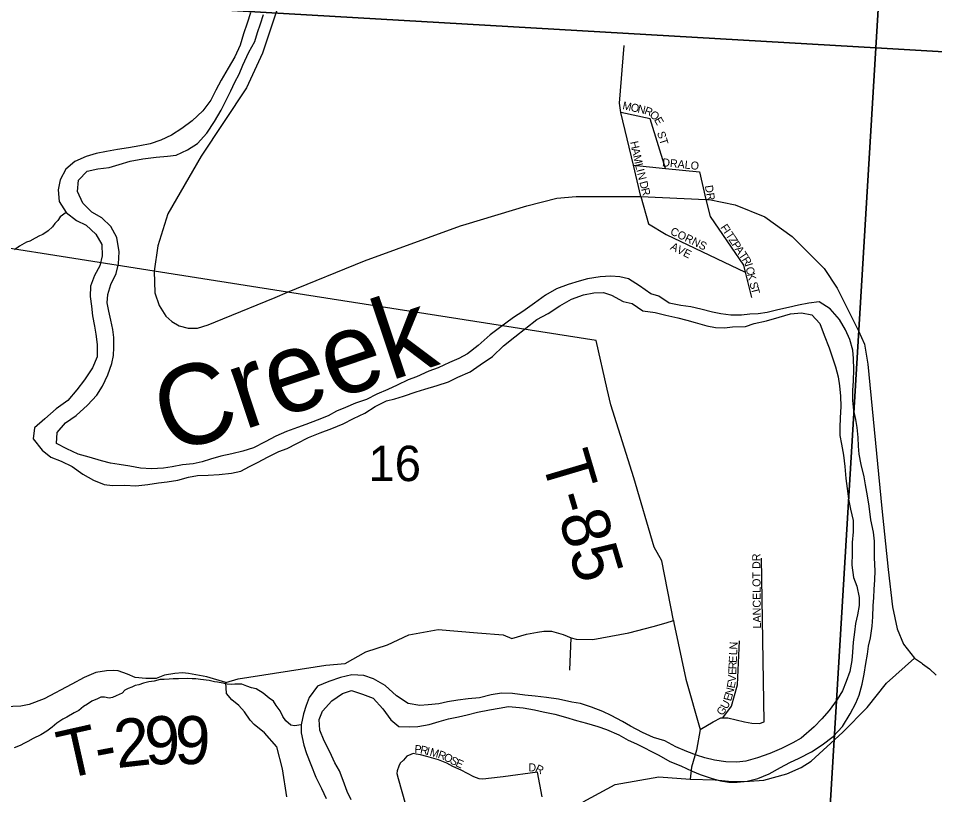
# Model space of a CAD drawing. Extents: x 0 to 34, y 0 to 22.
# Drawn here: x 4.831 to 5.915, y 18.127 to 19.045 of the extents above; entities that cross this region are included whole.
import ezdxf

# ---------------------------------------------------------------- set-up
doc = ezdxf.new("R2010")
doc.units = 0
for name, color, linetype in [('GM_X_County_Road', 7, 'Continuous'), ('GM_X_Major_River', 7, 'Continuous'), ('GM_X_Major_River_Text', 7, 'Continuous'), ('GM_X_Minor_River', 7, 'Continuous'), ('GM_X_Section', 7, 'Continuous'), ('GM_X_Section_Text', 7, 'Continuous'), ('GM_X_State_Route', 7, 'Continuous'), ('GM_X_Township_Road', 7, 'Continuous'), ('GM_X_Township_Road_Text', 7, 'Continuous'), ('GM_X_Township_ROW', 7, 'Continuous'), ('GM_X_Township_Subdivision', 7, 'Continuous'), ('GM_X_Township_Subdivision_Text', 7, 'Continuous')]:
    doc.layers.add(name, color=color, linetype=linetype)

msp = doc.modelspace()

# ---------------------------------------------------------------- linework, layer by layer
at = {"layer": 'GM_X_County_Road'}
for points in [[(5.1491, 18.1244), (5.1438, 18.1574), (5.137, 18.1832), (5.1226, 18.1999), (5.1104, 18.2098), (5.1055, 18.2151), (5.099, 18.2246), (5.0922, 18.2321), (5.0839, 18.239), (5.0774, 18.2466), (5.077, 18.2596), (5.0914, 18.2637), (5.1949, 18.28), (5.218, 18.2819), (5.2423, 18.2956), (5.2681, 18.304), (5.2931, 18.3158), (5.3279, 18.3222), (5.3746, 18.3181), (5.4049, 18.3158), (5.415, 18.3116), (5.4325, 18.3165), (5.4454, 18.3189), (5.4529, 18.3203), (5.4619, 18.3203), (5.476, 18.3163), (5.4852, 18.3125), (5.4911, 18.3107), (5.5109, 18.3104), (5.5535, 18.3184), (5.5824, 18.3259), (5.5975, 18.3302), (5.6064, 18.333), (5.6069, 18.3302)], [(5.6069, 18.3302), (5.6208, 18.2633), (5.6377, 18.2039), (5.6336, 18.1794), (5.6275, 18.1594), (5.6259, 18.145)], [(5.4994, 18.1185), (5.5373, 18.1387), (5.589, 18.1478), (5.6259, 18.145), (5.6557, 18.1442), (5.6713, 18.1427), (5.6906, 18.1423), (5.7133, 18.144), (5.7402, 18.1515), (5.7572, 18.1589), (5.769, 18.1664), (5.8067, 18.2007), (5.8355, 18.23), (5.8582, 18.2585), (5.8915, 18.2884)]]:
    msp.add_lwpolyline(points, dxfattribs=at)
at = {"layer": 'GM_X_Major_River'}
for points in [[(5.106, 19.0516), (5.1022, 19.0395), (5.0977, 19.0266), (5.0936, 19.0133), (5.0876, 18.9996), (5.0796, 18.986), (5.0714, 18.9719), (5.0649, 18.9602), (5.0589, 18.9484), (5.0495, 18.9358), (5.037, 18.9237), (5.0246, 18.9149), (5.0125, 18.9069), (5, 18.9008), (4.9875, 18.8966), (4.975, 18.8943), (4.9618, 18.892), (4.9485, 18.8901), (4.9357, 18.8877), (4.9236, 18.8851), (4.9115, 18.8816), (4.8982, 18.8759), (4.8877, 18.8668), (4.8809, 18.8542), (4.8783, 18.8421), (4.8798, 18.8284), (4.8878, 18.8156), (4.9003, 18.8061), (4.9117, 18.8005), (4.9231, 18.7899), (4.9303, 18.7774), (4.9307, 18.7641), (4.9277, 18.7524), (4.9213, 18.741), (4.9168, 18.7284), (4.9165, 18.7159), (4.918, 18.7046), (4.9192, 18.6932), (4.9215, 18.6811), (4.923, 18.6716), (4.9246, 18.6591), (4.9246, 18.6447), (4.919, 18.6318), (4.9095, 18.6173), (4.9005, 18.6055), (4.8899, 18.593), (4.8763, 18.5831), (4.8627, 18.5713), (4.8503, 18.5607), (4.8488, 18.5478), (4.8594, 18.5341), (4.87, 18.5262), (4.8822, 18.5213), (4.8951, 18.5149), (4.9076, 18.5058), (4.9201, 18.4987), (4.933, 18.4938), (4.9428, 18.4923), (4.9572, 18.4927)], [(4.9408, 18.799), (4.9302, 18.8092), (4.9185, 18.8157), (4.9078, 18.8266), (4.9014, 18.8403), (4.9025, 18.8535), (4.9127, 18.8642), (4.9255, 18.8672), (4.9388, 18.8688), (4.9505, 18.8722), (4.9637, 18.8761), (4.9785, 18.8788), (4.9944, 18.8807), (5.008, 18.8819), (5.0182, 18.8831), (5.0314, 18.8895), (5.0432, 18.8971), (5.0545, 18.9093), (5.0635, 18.923), (5.0714, 18.9363), (5.0771, 18.9484), (5.0827, 18.9594), (5.0873, 18.9697), (5.0925, 18.9792), (5.097, 18.9898), (5.1042, 19.005), (5.111, 19.0175), (5.1144, 19.0285), (5.1177, 19.0384), (5.1215, 19.0498)], [(5.8149, 18.6651), (5.8099, 18.6768), (5.8027, 18.689), (5.7917, 18.7014), (5.7788, 18.7097), (5.7663, 18.7082), (5.7542, 18.7059), (5.7425, 18.7032), (5.7296, 18.7001), (5.7171, 18.697), (5.7065, 18.6955), (5.6967, 18.6951), (5.6869, 18.6939), (5.674, 18.6939), (5.6623, 18.6954), (5.6524, 18.6976), (5.6388, 18.701), (5.627, 18.704), (5.6149, 18.7055), (5.6013, 18.7081), (5.5891, 18.7164), (5.5797, 18.7194), (5.566, 18.7288), (5.5531, 18.7371), (5.5429, 18.7394), (5.5323, 18.7401), (5.5194, 18.7393), (5.5047, 18.737), (5.4948, 18.7343), (5.4816, 18.7301), (5.468, 18.7251), (5.4551, 18.7175), (5.4419, 18.7083), (5.4283, 18.6984), (5.417, 18.6912), (5.4007, 18.679), (5.3894, 18.6707), (5.3754, 18.6581), (5.3626, 18.6482), (5.3524, 18.6429), (5.3414, 18.6379), (5.3278, 18.6318), (5.3168, 18.6276), (5.3025, 18.6211), (5.2926, 18.6173), (5.2794, 18.6112), (5.2684, 18.6062), (5.2556, 18.6005), (5.2431, 18.5944), (5.2302, 18.5898), (5.2185, 18.5848), (5.2076, 18.5803), (5.1977, 18.5749), (5.1849, 18.5696), (5.1713, 18.5646), (5.1614, 18.5612), (5.1486, 18.5562), (5.1361, 18.5509), (5.1232, 18.544), (5.1096, 18.5371), (5.0968, 18.5333), (5.0839, 18.5298), (5.071, 18.5272), (5.0586, 18.5237), (5.0487, 18.5206), (5.0381, 18.518), (5.0256, 18.5168), (5.0135, 18.5145), (5.0029, 18.5129), (4.9889, 18.5121), (4.9757, 18.5129), (4.9632, 18.5155), (4.9507, 18.5173), (4.9405, 18.5188), (4.9299, 18.5215), (4.9151, 18.526), (4.9022, 18.5297), (4.8889, 18.5357), (4.8764, 18.5422), (4.8775, 18.5551), (4.887, 18.5665), (4.8998, 18.5752), (4.913, 18.5874), (4.9243, 18.5995), (4.9308, 18.6098), (4.9372, 18.6235), (4.942, 18.6368), (4.9439, 18.6462), (4.9443, 18.6557), (4.9442, 18.6675), (4.9431, 18.677), (4.9408, 18.6879), (4.9385, 18.6986), (4.9365, 18.7084), (4.9373, 18.7183), (4.9406, 18.7304), (4.947, 18.7433), (4.95, 18.7547), (4.9508, 18.7687), (4.9477, 18.7858), (4.9408, 18.799)], [(4.9572, 18.4927), (4.9704, 18.492), (4.9844, 18.4935), (4.9973, 18.4955), (5.0075, 18.497), (5.02, 18.499), (5.0325, 18.5024), (5.0431, 18.5043), (5.056, 18.5047), (5.0688, 18.5055), (5.0836, 18.5071), (5.0946, 18.5094), (5.1048, 18.5151), (5.115, 18.5201), (5.1259, 18.5262), (5.1395, 18.5327), (5.1494, 18.5361), (5.1607, 18.5422), (5.1747, 18.5491), (5.1883, 18.5548), (5.2023, 18.5598), (5.2155, 18.5655), (5.228, 18.5716), (5.2412, 18.5781), (5.2533, 18.5861), (5.267, 18.5926), (5.2768, 18.5952), (5.287, 18.5983), (5.3021, 18.6033), (5.3123, 18.6063), (5.3267, 18.6106), (5.3403, 18.6151), (5.3513, 18.6205), (5.3657, 18.627), (5.3778, 18.6354), (5.3921, 18.6449), (5.4053, 18.6578), (5.4185, 18.6685), (5.4318, 18.6784), (5.4446, 18.689), (5.4582, 18.6959), (5.4718, 18.705), (5.4858, 18.713), (5.4998, 18.718), (5.5119, 18.7203), (5.5236, 18.7207), (5.5331, 18.7177), (5.5468, 18.7102), (5.5574, 18.7076), (5.5699, 18.6992), (5.5846, 18.697), (5.5971, 18.694), (5.6115, 18.6907), (5.6221, 18.688), (5.632, 18.6854), (5.6456, 18.6813), (5.6559, 18.6794), (5.6665, 18.6791), (5.6763, 18.6802), (5.6914, 18.6807), (5.7017, 18.6841), (5.7164, 18.6872), (5.7312, 18.6918), (5.7448, 18.6956), (5.7576, 18.6968), (5.7701, 18.6945), (5.7793, 18.6843), (5.7846, 18.6703), (5.7903, 18.6555), (5.7945, 18.6434), (5.7979, 18.6328), (5.801, 18.6211), (5.8025, 18.6105), (5.8037, 18.5983), (5.8041, 18.5858), (5.8034, 18.5725), (5.8031, 18.5612), (5.8031, 18.5517), (5.805, 18.5414), (5.8073, 18.5282), (5.8089, 18.5149), (5.81, 18.5009), (5.8116, 18.4891), (5.8135, 18.4762), (5.8158, 18.4645), (5.8189, 18.4512), (5.8189, 18.4376), (5.8178, 18.4251), (5.8175, 18.4125), (5.8171, 18.3981), (5.8191, 18.3837), (5.8232, 18.3735), (5.8259, 18.3602), (5.826, 18.3504), (5.8241, 18.3394), (5.8215, 18.3291), (5.8204, 18.3189), (5.8189, 18.3071), (5.8182, 18.2954), (5.8174, 18.2855), (5.8148, 18.2726)], [(5.2251, 18.1207), (5.2205, 18.1305), (5.2156, 18.1434), (5.2114, 18.1548), (5.2057, 18.1646), (5.1999, 18.1775), (5.1931, 18.1904), (5.1881, 18.2029), (5.1873, 18.2158), (5.1911, 18.2256), (5.2021, 18.2378), (5.2149, 18.2466), (5.2255, 18.25), (5.2384, 18.2455), (5.2509, 18.241), (5.2626, 18.2285), (5.2721, 18.2152), (5.2816, 18.2073), (5.2937, 18.207), (5.304, 18.2074), (5.3172, 18.2097), (5.3293, 18.2135), (5.3403, 18.2166), (5.352, 18.2189), (5.3622, 18.2212), (5.3743, 18.2243), (5.3887, 18.2273), (5.4001, 18.2293), (5.411, 18.2312), (5.4284, 18.2297), (5.4421, 18.2271), (5.4523, 18.2249), (5.4659, 18.2222), (5.4784, 18.2185), (5.4917, 18.2147), (5.5034, 18.2114), (5.5167, 18.2076), (5.5269, 18.2038), (5.5417, 18.1974), (5.5527, 18.1914), (5.5626, 18.1869), (5.5891, 18.1737), (5.602, 18.1661), (5.6149, 18.1609), (5.6285, 18.1545), (5.638, 18.1507), (5.6509, 18.1462), (5.6619, 18.1432), (5.6717, 18.1417), (5.6815, 18.1417), (5.6933, 18.1429), (5.7061, 18.146), (5.7194, 18.1513), (5.733, 18.1589), (5.7439, 18.165), (5.7549, 18.17), (5.7697, 18.1773), (5.7821, 18.1856), (5.7953, 18.1955), (5.8063, 18.2073), (5.8153, 18.2225), (5.8221, 18.2351), (5.8259, 18.2446), (5.8296, 18.2575), (5.8319, 18.2692), (5.8337, 18.2821), (5.8356, 18.2931), (5.8371, 18.3026), (5.8393, 18.3125), (5.8412, 18.3261), (5.8419, 18.3371), (5.8426, 18.35), (5.8433, 18.3599), (5.8437, 18.3694), (5.8444, 18.3808), (5.8448, 18.3914), (5.844, 18.4069), (5.8439, 18.4267), (5.8428, 18.4373), (5.8397, 18.4517), (5.8378, 18.468), (5.8358, 18.4801), (5.8335, 18.4934), (5.832, 18.5028), (5.8282, 18.5172), (5.8259, 18.5294), (5.8251, 18.5392), (5.8247, 18.5491), (5.8235, 18.5612), (5.822, 18.5707), (5.8197, 18.5813), (5.8185, 18.5931), (5.8185, 18.6048), (5.8192, 18.6162), (5.8195, 18.6298), (5.8191, 18.6427), (5.8183, 18.6526), (5.8149, 18.6651)], [(5.8148, 18.2726), (5.8107, 18.2608), (5.8062, 18.2498), (5.8001, 18.2395), (5.7903, 18.2262), (5.7817, 18.2164), (5.7726, 18.2069), (5.7575, 18.1935), (5.7473, 18.1882), (5.7341, 18.1813), (5.7204, 18.1756), (5.7057, 18.1702), (5.6917, 18.1664), (5.6811, 18.1652), (5.6682, 18.1656), (5.655, 18.1678), (5.6432, 18.1704), (5.6334, 18.1734), (5.622, 18.178), (5.6091, 18.1832), (5.5962, 18.1904), (5.5826, 18.1945), (5.5697, 18.2002), (5.5553, 18.2077), (5.5458, 18.2134), (5.5326, 18.2205), (5.5227, 18.2251), (5.5095, 18.2303), (5.4962, 18.2345), (5.486, 18.2363), (5.4701, 18.2397), (5.456, 18.2416), (5.4428, 18.2434), (5.4303, 18.2445), (5.4159, 18.2464), (5.403, 18.2467), (5.3905, 18.2448), (5.3769, 18.2413), (5.3633, 18.2402), (5.3512, 18.2386), (5.3391, 18.2367), (5.3289, 18.2344), (5.316, 18.2332), (5.3062, 18.2324), (5.2925, 18.2346), (5.2785, 18.2437), (5.2652, 18.2558), (5.2516, 18.2637), (5.2402, 18.2679), (5.2258, 18.2686), (5.2126, 18.2655), (5.1986, 18.2605), (5.1853, 18.2552), (5.1755, 18.2419), (5.1718, 18.2324), (5.1688, 18.2225), (5.1658, 18.2096), (5.1658, 18.2001), (5.1689, 18.1854), (5.1723, 18.1755), (5.1773, 18.1623), (5.1834, 18.1475), (5.1898, 18.1342), (5.1956, 18.1221)]]:
    msp.add_lwpolyline(points, dxfattribs=at)
at = {"layer": 'GM_X_Minor_River'}
for points in [[(4.8878, 18.8156), (4.8809, 18.8103), (4.8782, 18.8061), (4.8747, 18.8024), (4.8716, 18.7986), (4.8666, 18.7938), (4.8605, 18.7893), (4.8563, 18.7879), (4.8513, 18.7849), (4.8448, 18.7816), (4.841, 18.7802), (4.8329, 18.7757), (4.8268, 18.7713)], [(5.1658, 18.2096), (5.1582, 18.2081), (5.1537, 18.209), (5.1477, 18.214), (5.1444, 18.2194), (5.1411, 18.2259), (5.1363, 18.2321), (5.133, 18.2374), (5.1281, 18.2409), (5.121, 18.2467), (5.1128, 18.2518), (5.1071, 18.2531), (5.1018, 18.255), (5.0958, 18.2574), (5.092, 18.2575), (5.0875, 18.2576), (5.0833, 18.2573), (5.0784, 18.2577), (5.0731, 18.2586), (5.0671, 18.2598), (5.0633, 18.2603), (5.0572, 18.2619), (5.047, 18.2632), (5.0414, 18.2637), (5.0368, 18.2637), (5.0312, 18.2642), (5.0209, 18.264), (5.0145, 18.2637), (5.0099, 18.2634), (5.0039, 18.2632), (4.9993, 18.2632), (4.9921, 18.2611), (4.9856, 18.2604), (4.9795, 18.2586), (4.9738, 18.2568), (4.9696, 18.2558), (4.9658, 18.2539), (4.9612, 18.2525), (4.9574, 18.2506), (4.954, 18.2469), (4.9471, 18.2436), (4.9429, 18.2418), (4.9387, 18.2411), (4.9334, 18.2423), (4.9289, 18.242), (4.925, 18.2402), (4.9182, 18.2373), (4.9132, 18.2339), (4.9086, 18.231), (4.9028, 18.2265), (4.8975, 18.2236), (4.8887, 18.2184), (4.8841, 18.2162), (4.8768, 18.2114), (4.8714, 18.2065), (4.8649, 18.2021), (4.858, 18.1976), (4.8488, 18.1932), (4.8427, 18.1895), (4.8385, 18.1877), (4.8335, 18.1851), (4.8263, 18.1822)]]:
    msp.add_lwpolyline(points, dxfattribs=at)
at = {"layer": 'GM_X_Section'}
for points in [[(4.8284, 20.0797), (5.9068, 20.018), (5.8458, 19.0101), (4.7704, 19.0729)], [(5.9068, 20.018), (6.9795, 19.9566), (6.9173, 18.9472), (5.8458, 19.0101)], [(5.8458, 19.0101), (5.784, 17.9889), (4.7124, 18.0487), (4.7704, 19.0729)], [(6.9173, 18.9472), (6.8533, 17.9287), (5.784, 17.9889), (5.8458, 19.0101)]]:
    msp.add_lwpolyline(points, close=True, dxfattribs=at)
at = {"layer": 'GM_X_State_Route'}
for points in [[(5.1406, 19.0654), (5.1202, 19.0037), (5.1014, 18.9628), (5.0475, 18.8821), (5.0084, 18.814), (4.9965, 18.776), (4.992, 18.7459), (4.9929, 18.7203), (4.9978, 18.7054), (5.0059, 18.6926), (5.0129, 18.6864), (5.0215, 18.6813), (5.0321, 18.6784), (5.0431, 18.6785), (5.0561, 18.6827), (5.0733, 18.6895), (5.135, 18.715), (5.1499, 18.7211), (5.2407, 18.7584), (5.3543, 18.7997), (5.3609, 18.8017)], [(5.3609, 18.8017), (5.433, 18.8233), (5.4685, 18.8323), (5.4913, 18.8344), (5.5677, 18.8345), (5.6444, 18.8309), (5.6486, 18.8307), (5.6792, 18.8243), (5.7145, 18.8102), (5.7466, 18.787), (5.7844, 18.749), (5.7998, 18.7258), (5.8251, 18.6755), (5.8323, 18.6598), (5.836, 18.6362), (5.8528, 18.4654), (5.8602, 18.3931), (5.8652, 18.349), (5.8707, 18.323), (5.8782, 18.305), (5.8915, 18.2884), (5.8995, 18.2826)], [(5.8995, 18.2826), (5.9008, 18.2817), (5.909, 18.2758), (5.9172, 18.268)]]:
    msp.add_lwpolyline(points, dxfattribs=at)
at = {"layer": 'GM_X_Township_Road'}
for points in [[(5.6064, 18.333), (5.5924, 18.4035), (5.5833, 18.4196), (5.5594, 18.5015), (5.5321, 18.588), (5.5279, 18.6064)], [(5.4838, 18.2742), (5.4852, 18.3125)], [(5.077, 18.2596), (5.0542, 18.2661), (5.0328, 18.2703), (5.0255, 18.2711), (5.0165, 18.2703), (5.0041, 18.2683), (4.9945, 18.2644), (4.9821, 18.2644), (4.9694, 18.2655), (4.9604, 18.2692), (4.9494, 18.2731), (4.9438, 18.2737), (4.9356, 18.2731), (4.9232, 18.2714), (4.9094, 18.2655), (4.8945, 18.2576), (4.8621, 18.2401), (4.8441, 18.2334), (4.8345, 18.2314), (4.8153, 18.2308)]]:
    msp.add_lwpolyline(points, dxfattribs=at)
at = {"layer": 'GM_X_Township_ROW'}
msp.add_lwpolyline([(5.5279, 18.6064), (5.5147, 18.6639), (5.1499, 18.7211), (4.992, 18.7459), (4.8017, 18.7758), (4.7835, 18.7727), (4.7573, 18.7814), (4.725, 18.8079), (4.7045, 18.8366), (4.7, 18.8515)], dxfattribs=at)
at = {"layer": 'GM_X_Township_Subdivision'}
for points in [[(5.5677, 18.8345), (5.5591, 18.8713), (5.5441, 18.9337), (5.5424, 18.9449), (5.5479, 19.0129)], [(5.5967, 18.8675), (5.5787, 18.9261), (5.5441, 18.9337)], [(5.5591, 18.8713), (5.5967, 18.8675), (5.6371, 18.8635), (5.6444, 18.8309)], [(5.5677, 18.8345), (5.5766, 18.802), (5.5978, 18.7892), (5.6912, 18.7447)], [(5.6444, 18.8309), (5.6498, 18.8105), (5.6891, 18.7532), (5.6912, 18.7447), (5.6986, 18.715)], [(5.6377, 18.2039), (5.6532, 18.2128), (5.6623, 18.2177), (5.6646, 18.2177), (5.6706, 18.2177), (5.6903, 18.2128), (5.6991, 18.2113), (5.7082, 18.2109), (5.7135, 18.2128), (5.7104, 18.4064)], [(5.6646, 18.2177), (5.6748, 18.2314), (5.682, 18.2568), (5.6842, 18.3088)], [(5.451, 18.1241), (5.4456, 18.1533), (5.4047, 18.1479), (5.3876, 18.1461), (5.3844, 18.1457), (5.3804, 18.1452), (5.3763, 18.1457), (5.37, 18.1479), (5.3552, 18.1556), (5.3453, 18.1601), (5.3381, 18.1641), (5.3282, 18.1682), (5.3147, 18.1718), (5.307, 18.174), (5.3021, 18.1749), (5.2985, 18.1754), (5.2958, 18.1745), (5.2908, 18.1722), (5.2868, 18.1677), (5.2832, 18.1641), (5.2814, 18.1605), (5.2796, 18.1551), (5.2791, 18.152), (5.2805, 18.1461), (5.2895, 18.1151)]]:
    msp.add_lwpolyline(points, dxfattribs=at)

# ---------------------------------------------------------------- texts
at = {"layer": 'GM_X_Major_River_Text'}
msp.add_text('Creek', height=0.0947, rotation=18.5141, dxfattribs=at).set_placement((5.0109, 18.5289))
at = {"layer": 'GM_X_Section_Text'}
msp.add_text('16', height=0.04186, rotation=0, dxfattribs=at).set_placement((5.2454, 18.4977))
at = {"layer": 'GM_X_Township_Road_Text'}
for s, height, rotation, p in [('T-85', 0.05682, 286.5301, (5.4496, 18.5237)), ('9', 0.0568, 2.4278, (4.9817, 18.162)), ('9', 0.0568, 358.4341, (5.0156, 18.1635)), ('T', 0.0568, 12.6256, (4.8852, 18.1448)), ('2', 0.0568, 6.4931, (4.948, 18.1581)), ('-', 0.0568, 10.7319, (4.9262, 18.154))]:
    msp.add_text(s, height=height, rotation=rotation, dxfattribs=at).set_placement(p)
at = {"layer": 'GM_X_Township_Subdivision_Text'}
for s, rotation, p in [('M', 347.9059, (5.5454, 18.9377)), ('O', 347.9059, (5.5551, 18.9356)), ('N', 347.9059, (5.5633, 18.9339)), ('R', 338.16, (5.571, 18.9323)), ('O', 318.6682, (5.5773, 18.9299)), ('E', 299.1764, (5.583, 18.9251)), ('ST', 287.3453, (5.5867, 18.9098)), ('H', 281.9995, (5.555, 18.8988)), ('A', 281.999, (5.5567, 18.8906)), ('M', 282.157, (5.5585, 18.8825)), ('L', 283.6124, (5.5606, 18.8724)), ('DRALO', 354.053, (5.5926, 18.8702)), ('I', 284.2619, (5.5622, 18.8658)), ('N', 284.3529, (5.5633, 18.8618)), ('D', 284.3563, (5.5659, 18.8513)), ('R', 284.3322, (5.568, 18.8432)), ('DR', 278.979, (5.6434, 18.847)), ('CORNS', 334.5366, (5.6016, 18.79)), ('F', 303.6162, (5.6614, 18.7978)), ('I', 303.6361, (5.6651, 18.7922)), ('T', 303.62, (5.6674, 18.7887)), ('Z', 303.6413, (5.6711, 18.7832)), ('AVE', 333.4324, (5.6018, 18.7721)), ('P', 303.6143, (5.6748, 18.7776)), ('A', 303.6128, (5.6785, 18.7721)), ('T', 303.6231, (5.6831, 18.7652)), ('R', 301.5041, (5.6868, 18.7597)), ('I', 287.3583, (5.6904, 18.7538)), ('C', 282.733, (5.6916, 18.7501)), ('K', 284.2442, (5.6933, 18.7425)), ('S', 284.4131, (5.696, 18.732)), ('T', 284.4362, (5.6977, 18.7255)), ('LANCELOT DR', 90.5965, (5.7098, 18.3234)), ('N', 87.1793, (5.6819, 18.2983)), ('L', 87.1848, (5.6815, 18.2916)), ('E', 87.1844, (5.6811, 18.2825)), ('E', 87.1827, (5.6804, 18.2683)), ('R', 87.1818, (5.6807, 18.275)), ('V', 86.4559, (5.6799, 18.2599)), ('N', 75.3053, (5.6762, 18.2433)), ('E', 78.9439, (5.6784, 18.252)), ('E', 75.1194, (5.6744, 18.2368)), ('G', 55.8871, (5.6643, 18.2195)), ('U', 61.1999, (5.6695, 18.2272)), ('P', 357.1274, (5.2998, 18.1761)), ('R', 348.0931, (5.3061, 18.1758)), ('I', 345.407, (5.3133, 18.1742)), ('M', 344.4262, (5.3173, 18.1732)), ('R', 340.2682, (5.3268, 18.1706)), ('O', 334.4319, (5.3336, 18.1681)), ('S', 330.8104, (5.341, 18.1646)), ('E', 336.3345, (5.3477, 18.1609)), ('D', 359.0464, (5.4346, 18.1544)), ('R', 334.3175, (5.4419, 18.1545))]:
    msp.add_text(s, height=0.00947, rotation=rotation, dxfattribs=at).set_placement(p)

doc.saveas('drawing.dxf')
